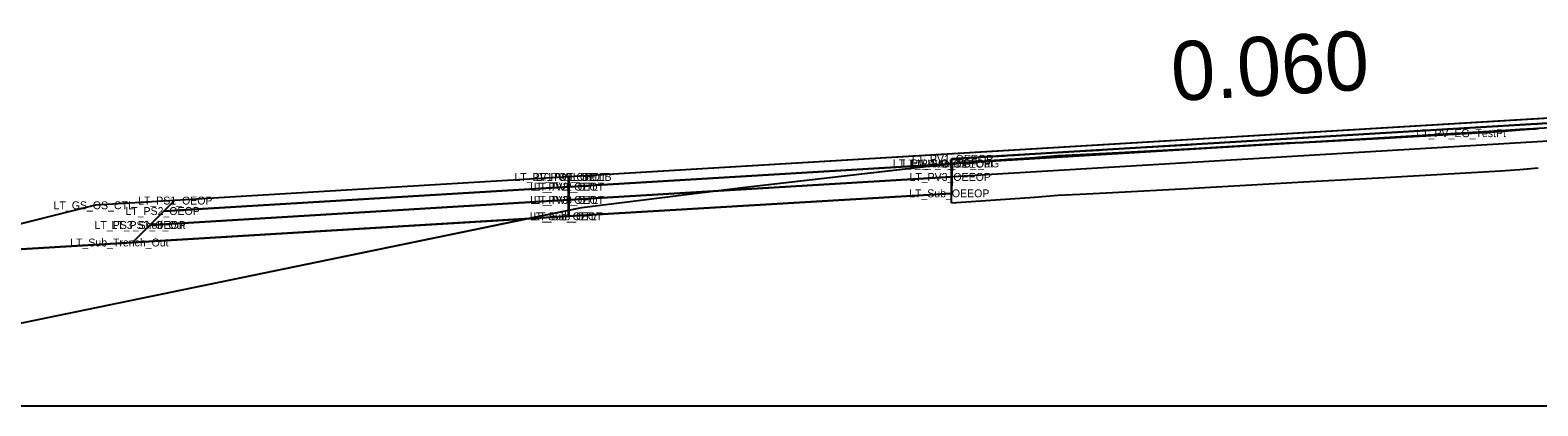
# Model space of a CAD drawing. Extents: x 2177029 to 2201446, y 59897 to 78390.
# Drawn here: x 2200163.06 to 2200201.31, y 68407.31 to 68416.84 of the extents above; entities that cross this region are included whole.
import ezdxf

# ---------------------------------------------------------------- set-up
doc = ezdxf.new("R2010")
doc.units = 0
for name, color, linetype in [('Exist Cross Section Cell', 7, 'Continuous'), ('Exist PHM Roadway Shape', 7, 'Continuous'), ('Exist XS Ground Line', 7, 'Continuous'), ('Old_Level_11', 7, 'Continuous'), ('Prop CMT Conc Surface', 7, 'Continuous'), ('Prop CMT Concrete Structures', 7, 'Continuous'), ('Prop CMT Guardrail Graphics', 7, 'Continuous'), ('Prop CMT Pvmt Course 1', 7, 'Continuous'), ('Prop CMT Pvmt Course 1 CG', 7, 'Continuous'), ('Prop CMT Pvmt Course 2', 7, 'Continuous'), ('Prop CMT Pvmt Course 2 CG', 7, 'Continuous'), ('Prop CMT Pvmt Course 3', 7, 'Continuous'), ('Prop CMT Pvmt Course 4', 7, 'Continuous'), ('Prop CMT Pvmt Surface', 7, 'Continuous'), ('Prop CMT Pvmt Wedge Surface 1', 7, 'Continuous'), ('Prop CMT Slope Grass', 7, 'Continuous'), ('Prop CMT Subgrade Earthwork', 7, 'Continuous'), ('Prop Hatching', 7, 'Continuous'), ('Prop XS Side Slope Text', 7, 'Continuous'), ('Scratch_Level_0', 7, 'Continuous'), ('Scratch_Level_9', 7, 'Continuous')]:
    doc.layers.add(name, color=color, linetype=linetype)

msp = doc.modelspace()

# ---------------------------------------------------------------- linework, layer by layer
at = {"layer": 'Exist Cross Section Cell'}
msp.add_line((2200042.732, 68407.31), (2200242.732, 68407.31), dxfattribs=at)
at = {"layer": 'Exist XS Ground Line'}
msp.add_lwpolyline([(2200160.025, 68408.835), (2200177.055, 68412.347), (2200181.137, 68412.847), (2200186.438, 68413.461), (2200188.047, 68413.572), (2200188.545, 68413.607), (2200189.135, 68413.653), (2200189.69, 68413.68), (2200190.363, 68413.713), (2200192.434, 68413.826), (2200192.863, 68413.85), (2200194.931, 68413.972), (2200195.363, 68413.996), (2200197.429, 68414.106), (2200197.863, 68414.128), (2200199.926, 68414.249), (2200200.363, 68414.274), (2200200.854, 68414.311), (2200201.316, 68414.346)], dxfattribs=at)
at = {"layer": 'Prop CMT Conc Surface'}
for points in [[(2200212.732, 68415.155), (2200186.438, 68413.577)], [(2200186.438, 68413.452), (2200176.732, 68412.87)], [(2200186.438, 68413.577), (2200186.438, 68413.452)], [(2200176.732, 68412.87), (2200176.732, 68413.12)]]:
    msp.add_lwpolyline(points, dxfattribs=at)
at = {"layer": 'Prop CMT Concrete Structures'}
for p, q in [((2200212.732, 68415.28), (2200176.732, 68413.12)), ((2200176.732, 68413.12), (2200176.722, 68413.119))]:
    msp.add_line(p, q, dxfattribs=at)
at = {"layer": 'Prop CMT Guardrail Graphics'}
for points in [[(2200212.732, 68414.696), (2200176.732, 68412.536)], [(2200176.732, 68412.536), (2200176.732, 68413.12)]]:
    msp.add_lwpolyline(points, dxfattribs=at)
at = {"layer": 'Prop CMT Pvmt Course 1'}
for points in [[(2200201.302, 68414.344), (2200201.249, 68414.34), (2200201.199, 68414.336), (2200200.854, 68414.311), (2200200.363, 68414.274), (2200199.927, 68414.249), (2200197.863, 68414.128), (2200197.429, 68414.106), (2200196.534, 68414.058)], [(2200196.534, 68414.058), (2200197.429, 68414.112)], [(2200197.429, 68414.112), (2200197.863, 68414.138), (2200199.927, 68414.262), (2200200.363, 68414.288), (2200200.854, 68414.318), (2200201.199, 68414.338), (2200201.249, 68414.341), (2200201.302, 68414.344)]]:
    msp.add_lwpolyline(points, dxfattribs=at)
at = {"layer": 'Prop CMT Pvmt Course 1 CG'}
for points in [[(2200176.722, 68412.536), (2200166.101, 68411.898)], [(2200176.722, 68412.119), (2200176.722, 68412.536)], [(2200165.658, 68411.455), (2200176.722, 68412.119)], [(2200166.101, 68411.898), (2200165.658, 68411.455)], [(2200166.101, 68411.898), (2200166.101, 68411.898)]]:
    msp.add_lwpolyline(points, dxfattribs=at)
at = {"layer": 'Prop CMT Pvmt Course 2'}
for points in [[(2200186.438, 68413.119), (2200176.732, 68412.536)], [(2200186.438, 68412.702), (2200186.438, 68413.119)], [(2200176.732, 68412.536), (2200176.722, 68412.536)], [(2200176.722, 68412.536), (2200176.722, 68412.119)], [(2200176.732, 68412.12), (2200186.438, 68412.702)], [(2200176.732, 68412.12), (2200176.732, 68412.536)], [(2200176.732, 68412.536), (2200176.732, 68412.12)], [(2200176.722, 68412.119), (2200176.732, 68412.12)]]:
    msp.add_lwpolyline(points, dxfattribs=at)
at = {"layer": 'Prop CMT Pvmt Course 2 CG'}
for points in [[(2200212.732, 68415.28), (2200176.732, 68413.12)], [(2200186.438, 68413.577), (2200212.732, 68415.155)], [(2200176.732, 68412.87), (2200186.438, 68413.452)], [(2200186.438, 68413.452), (2200186.438, 68413.577)], [(2200176.732, 68413.12), (2200176.724, 68413.119), (2200176.722, 68413.119)], [(2200176.722, 68413.119), (2200176.722, 68412.869)], [(2200176.732, 68412.87), (2200176.732, 68413.12)], [(2200176.732, 68413.12), (2200176.732, 68412.87)], [(2200176.722, 68412.869), (2200176.732, 68412.87)]]:
    msp.add_lwpolyline(points, dxfattribs=at)
at = {"layer": 'Prop CMT Pvmt Course 3'}
for points in [[(2200186.438, 68412.702), (2200186.454, 68413.462)], [(2200186.438, 68412.702), (2200176.732, 68412.12)], [(2200176.722, 68412.119), (2200165.658, 68411.455)], [(2200176.732, 68412.12), (2200176.722, 68412.119)], [(2200165.658, 68411.455), (2200159.459, 68411.083)]]:
    msp.add_lwpolyline(points, dxfattribs=at)
at = {"layer": 'Prop CMT Pvmt Course 4'}
msp.add_lwpolyline([(2200176.722, 68413.119), (2200166.722, 68412.519)], dxfattribs=at)
at = {"layer": 'Prop CMT Pvmt Surface'}
for points in [[(2200186.438, 68413.577), (2200187.777, 68413.658), (2200187.863, 68413.663), (2200188.047, 68413.674), (2200188.545, 68413.704), (2200189.135, 68413.739), (2200189.69, 68413.773), (2200190.18, 68413.802), (2200190.363, 68413.813), (2200192.434, 68413.937), (2200192.863, 68413.963), (2200194.931, 68414.087), (2200195.363, 68414.113), (2200197.429, 68414.237), (2200197.863, 68414.263), (2200199.927, 68414.387), (2200200.363, 68414.413), (2200200.854, 68414.443), (2200201.199, 68414.463), (2200201.249, 68414.466), (2200201.316, 68414.47)], [(2200201.316, 68414.346), (2200201.302, 68414.344), (2200201.249, 68414.341), (2200201.199, 68414.338), (2200200.854, 68414.318), (2200200.363, 68414.288), (2200199.927, 68414.262), (2200197.863, 68414.138), (2200197.429, 68414.112), (2200196.534, 68414.058), (2200195.363, 68413.996), (2200194.931, 68413.972), (2200192.863, 68413.85), (2200192.434, 68413.826), (2200190.363, 68413.713), (2200190.18, 68413.704), (2200189.69, 68413.68), (2200189.135, 68413.653), (2200188.545, 68413.607), (2200188.047, 68413.572), (2200187.863, 68413.558), (2200187.777, 68413.553), (2200186.438, 68413.461)], [(2200186.438, 68413.461), (2200186.438, 68413.577)]]:
    msp.add_lwpolyline(points, dxfattribs=at)
at = {"layer": 'Prop CMT Pvmt Wedge Surface 1'}
for p, q in [((2200186.438, 68412.461), (2200186.438, 68413.461)), ((2200199.926, 68413.249), (2200200.363, 68413.274)), ((2200200.363, 68413.274), (2200200.854, 68413.311)), ((2200200.854, 68413.311), (2200201.316, 68413.346)), ((2200192.863, 68412.85), (2200194.931, 68412.972)), ((2200194.931, 68412.972), (2200195.363, 68412.996)), ((2200195.363, 68412.996), (2200197.429, 68413.106)), ((2200197.429, 68413.106), (2200197.863, 68413.128)), ((2200197.863, 68413.128), (2200199.926, 68413.249)), ((2200186.438, 68412.461), (2200188.047, 68412.572)), ((2200188.047, 68412.572), (2200188.545, 68412.607)), ((2200188.545, 68412.607), (2200189.135, 68412.653)), ((2200189.135, 68412.653), (2200189.69, 68412.68)), ((2200189.69, 68412.68), (2200190.363, 68412.713)), ((2200190.363, 68412.713), (2200192.434, 68412.826)), ((2200192.434, 68412.826), (2200192.863, 68412.85))]:
    msp.add_line(p, q, dxfattribs=at)
at = {"layer": 'Prop CMT Slope Grass'}
for points in [[(2200186.438, 68413.452), (2200176.732, 68412.87)], [(2200186.438, 68413.119), (2200186.438, 68413.452)], [(2200176.732, 68412.536), (2200186.438, 68413.119)], [(2200176.732, 68412.87), (2200176.722, 68412.869)], [(2200176.722, 68412.869), (2200176.722, 68412.536)], [(2200176.722, 68412.536), (2200176.732, 68412.536)], [(2200176.732, 68412.536), (2200176.732, 68412.87)], [(2200176.732, 68412.87), (2200176.732, 68412.536)]]:
    msp.add_lwpolyline(points, dxfattribs=at)
at = {"layer": 'Prop CMT Subgrade Earthwork'}
for points in [[(2200212.732, 68415.03), (2200176.732, 68412.87)], [(2200176.732, 68412.87), (2200176.732, 68413.12)]]:
    msp.add_lwpolyline(points, dxfattribs=at)
at = {"layer": 'Prop Hatching'}
msp.add_lwpolyline([(2200166.722, 68412.519), (2200164.722, 68412.399), (2200146.806, 68407.92)], dxfattribs=at)
at = {"layer": 'Prop XS Side Slope Text'}
msp.add_lwpolyline([(2200212.732, 68415.28), (2200176.722, 68413.119), (2200166.722, 68412.519), (2200164.722, 68412.399), (2200159.457, 68411.083), (2200165.658, 68411.455), (2200175.636, 68412.055), (2200177.055, 68412.347), (2200181.137, 68412.847), (2200186.454, 68413.462), (2200188.047, 68413.572), (2200188.545, 68413.607), (2200189.135, 68413.653), (2200189.69, 68413.68), (2200190.363, 68413.713), (2200192.434, 68413.826), (2200192.863, 68413.85), (2200194.931, 68413.972), (2200195.363, 68413.996), (2200197.429, 68414.106), (2200197.863, 68414.128), (2200199.926, 68414.249), (2200200.363, 68414.274), (2200200.854, 68414.311), (2200201.316, 68414.346)], dxfattribs=at)
for points in [[(2200177.055, 68412.347), (2200181.137, 68412.847), (2200186.454, 68413.462), (2200186.438, 68412.702), (2200176.732, 68412.12), (2200175.636, 68412.055)], [(2200150.493, 68407.998), (2200153.53, 68407.974), (2200155.825, 68408.008), (2200160.025, 68408.835), (2200175.636, 68412.055), (2200165.658, 68411.455), (2200159.457, 68411.083), (2200149.174, 68408.512)]]:
    msp.add_lwpolyline(points, close=True, dxfattribs=at)
at = {"layer": 'Scratch_Level_0'}
for points in [[(2200176.722, 68412.869), (2200166.457, 68412.253), (2200166.101, 68411.898)], [(2200166.101, 68411.898), (2200176.722, 68412.536)], [(2200176.722, 68412.536), (2200176.722, 68412.869)]]:
    msp.add_lwpolyline(points, dxfattribs=at)
at = {"layer": 'Scratch_Level_9'}
for points in [[(2200176.722, 68413.119), (2200166.722, 68412.519), (2200166.457, 68412.253)], [(2200176.722, 68412.869), (2200176.722, 68413.119)], [(2200166.457, 68412.253), (2200176.722, 68412.869)]]:
    msp.add_lwpolyline(points, dxfattribs=at)

# ---------------------------------------------------------------- texts
at = {"layer": 'Exist PHM Roadway Shape'}
for s, p in [('LT_PV_EG_TestPt', (2200198.226, 68414.129)), ('LT_PV1_OEEOP', (2200185.426, 68413.477)), ('LT_PV_Sub_Tie_Out', (2200184.948, 68413.362)), ('LT_PV_OEEOP_EG', (2200185.193, 68413.361)), ('LT_PV2_OEEOP', (2200185.369, 68413.352)), ('LT_PV1_OTL SE LB', (2200175.347, 68413.019)), ('LT_PV2_OEOT', (2200175.749, 68412.77)), ('LT_PV1_OEOT', (2200175.806, 68413.02)), ('LT_PV2_OTL', (2200175.837, 68412.769)), ('LT_PV1_OTL', (2200175.894, 68413.019)), ('LT_PV3_OEEOP', (2200185.369, 68413.019)), ('LT_PS1_OEOP', (2200165.802, 68412.419)), ('LT_PV3_OEOT', (2200175.749, 68412.436)), ('LT_PV3_OTL', (2200175.837, 68412.436)), ('LT_Sub_OEEOP', (2200185.36, 68412.602)), ('LT_GS_OS_CTL', (2200163.659, 68412.299)), ('LT_PS2_OEOP', (2200165.48, 68412.153)), ('LT_Sub_OEOT', (2200175.74, 68412.02)), ('LT_Sub_OTL', (2200175.828, 68412.019)), ('LT_PS3_Shelf_Out', (2200164.699, 68411.798)), ('LT_PS3_OEOP', (2200165.125, 68411.798)), ('LT_Sub_Trench_Out', (2200164.079, 68411.355))]:
    msp.add_text(s, height=0.2, dxfattribs=at).set_placement(p)
at = {"layer": 'Old_Level_11'}
msp.add_text('0.060', height=1.5, rotation=3.4337, dxfattribs=at).set_placement((2200192.052, 68415.041))

doc.saveas('drawing.dxf')
